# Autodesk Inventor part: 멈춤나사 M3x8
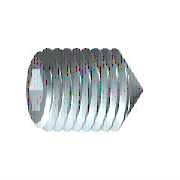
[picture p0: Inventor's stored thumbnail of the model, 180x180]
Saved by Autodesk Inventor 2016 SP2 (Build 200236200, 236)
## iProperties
IsCustomPart: 1
Created: 2012-02
Part Number: 멈춤나사 M3x8
Material: 강철, 연강
Description: 6각 소켓 머리 없는 멈춤 나사
Document SubType Name: Modeling
Standard: KS B 1028
Designer: test
Standards Organization: KS
Language: ko-KR
Size Designation: 원추점 M3x8
Categories: <MemberInstance><Categories><Category DisplayName="조임쇠" InternalName="e4da775c-781d-43d5-af7c-5136215cf5a6" Mnemonic="FSTN"><Category DisplayName="볼트" InternalN
Density: 1 g/cm^3
Appearance: 강철
Author: test
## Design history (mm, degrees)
sketch "스케치1"
  geometry: L1 (0, 0)-(5.5, 0); L2 (8, 0.866)-(8, 1.5); L3 (8, 1.5)-(0, 1.5); L4 (8, 0.866)-(6, 0.866); L5 (6, 0.866)-(5.5, 0); L6 (0, -0.3)-(0, 1.8) reference; L7 (0, 1.5)-(0, 0)
  constraints: 13 end point, 3 parallel, 1 collinear, 1 perpendicular, 1 point on line
  dimensions: "d0" = 2 distance of L2.start L4.end (= INTI); "d1" = 60 deg angle of L5 L1; "d2" = 3 diameter of L3 L1 (= NND); "d3" = 1.73205 diameter of L4 L1 (= 1.1547 x SW); "d5" = 8 distance from line of L2 L3.end (= NLG)
revolve "본체" sketch "스케치1" stored, may be unused: angle "d6" = 90 deg
sketch "스케치2"
  geometry: L1 (-0.433, 0.75)-(0.433, 0.75); L2 (0.433, 0.75)-(0.866, 0); L3 (0.866, 0)-(0.433, -0.75); L4 (0.433, -0.75)-(-0.433, -0.75); L5 (-0.433, -0.75)-(-0.866, 0); L6 (-0.866, 0)-(-0.433, 0.75); 3 further points
  constraints: 12 end point, 1 coincident, 1 horizontal, 13 other
extrude "슬롯" join sketch "스케치2" taper "d7" = 0 deg; stored distance "d21" = 10
workaxis "Work Axis1"
workplane "Work Plane1"
sketch "스케치4"
  geometry: L1 (0, 0.15)-(-1.35, 1.5) reference; L2 (0, -0.15)-(-1.35, -1.5) reference; L3 (-1.35, -1.5)-(0.15, 0); L4 (-1.35, 1.5)-(0.15, 0); 2 further points
  constraints: 4 end point, 1 coincident, 1 collinear, 1 horizontal alignment
body "Solid1"
feature "스레드" dims "d12" = 8 (= NLG), "d13" = 0
chamfer "모따기1" distance "d8" = 1.35 (computed from NND, SPD, FAWI); stored, may be unused: angle "d9" = 45 deg (= FAWI), second distance "d34" = 1.35 (computed from NND, SPD, FAWI)
chamfer "모따기2" distance "d10" = 0.30673 (= -0.5 x GD1 + 0.5 x NND); stored, may be unused: angle "d11" = 45 deg (= FAWI), second distance "d35" = 0.30673 (= -0.5 x GD1 + 0.5 x NND)
other parameters: "NND" = 3 [user parameter; used in 5 equation terms], "NLG" = 8 [user parameter; used in 2 equation terms], "INTI" = 2 [user parameter; used in 1 equation term], "FAWI" = 45 deg [user parameter; used in 4 equation terms], "SW" = 1.5 [user parameter; used in 2 equation terms], "GD1" = 2.38655 (= THREADDIA - 1.2269 x PTC) [user parameter; used in 2 equation terms], "d4" = 0, "FAWI1" = 45 deg [user parameter], "SPD" = 0.3 [user parameter; used in 2 equation terms], "d36" = 0, "d37" = 0, "GUL" = 0.30673 (= 0.61345 x PTC) [user parameter], "TOA" = 30 deg [user parameter], "THREADDIA" = 3 [user parameter; used in 1 equation term], "PTC" = 0.5 [user parameter; used in 4 equation terms], "GAL" = 0.30673 (= 0.61345 x PTC) [user parameter], "E0" = 1.7325 (= 1.155 x SW) [user parameter]
